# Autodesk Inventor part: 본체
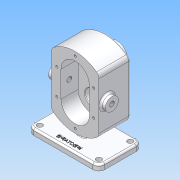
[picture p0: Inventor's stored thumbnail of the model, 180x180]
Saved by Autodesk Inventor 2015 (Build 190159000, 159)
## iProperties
Created: 2019-03
Part Number: 본체
Material: 일반
Document SubType Name: Modeling
Designer: user
Density: 1 g/cm^3
Appearance: 기본값
Mass: 439.69 g
Surface Area: 719.273 cm^2
Volume: 439.69 cm^3
Author: user
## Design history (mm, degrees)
sketch "스케치1"
  geometry: L1 (-60, 36.5)-(60, 36.5); L2 (60, 36.5)-(60, -36.5); L3 (60, -36.5)-(-60, -36.5); L4 (-60, -36.5)-(-60, 36.5); L5 (-60, 36.5)-(60, -36.5); L6 (60, 36.5)-(-60, -36.5); 1 further point
  constraints: 12 end point, 2 midpoint, 2 parallel, 1 horizontal, 1 perpendicular
  dimensions: "d0" = 120 distance of L2.end L3.end; "d1" = 73 distance of L1.end L2.end
extrude "돌출1" new body sketch "스케치1" distance "d2" = 10; taper "d3" = 0 deg
fillet "모깎기1" dims "d4" = 10
hole "구멍1" diameter "d8" = 9; stored, may be unused: countersink angle "d12" = 90 deg, drill point angle "d14" = 0 deg; dims "d6" = 10, "d7" = 10, "d9" = 6, "d10" = 4, "d11" = 2, "d13" = 8
hole "구멍2" diameter "d17" = 9; stored, may be unused: countersink angle "d21" = 90 deg, drill point angle "d23" = 0 deg; dims "d15" = 10, "d16" = 10, "d18" = 6, "d19" = 4, "d20" = 2, "d22" = 8
hole "구멍3" diameter "d26" = 9; stored, may be unused: countersink angle "d30" = 90 deg, drill point angle "d32" = 0 deg; dims "d24" = 10, "d25" = 10, "d27" = 6, "d28" = 4, "d29" = 2, "d31" = 8
hole "구멍4" diameter "d35" = 9; stored, may be unused: countersink angle "d39" = 90 deg, drill point angle "d41" = 0 deg; dims "d33" = 10, "d34" = 10, "d36" = 6, "d37" = 4, "d38" = 2, "d40" = 8
sketch "스케치2"
  geometry: L1 (50, 36.5)-(-50, 36.5) reference; L2 (-6, -6.5)-(6, -6.5); L3 (6, -6.5)-(6, 36.5); L4 (6, 36.5)-(-6, 36.5); L5 (-6, 36.5)-(-6, -6.5); 2 further points
  constraints: 8 end point, 2 midpoint, 2 parallel, 1 horizontal, 1 perpendicular, 1 point on line
  dimensions: "d42" = 43 distance of L2.end L3.end; "d43" = 12 distance of L2.start L2.end
extrude "돌출2" join sketch "스케치2" distance "d44" = 30; taper "d45" = 0 deg
fillet "모깎기3" dims "d46" = 3
sketch "스케치3"
  geometry: L1 (0, 0)-(100, 0) reference; L2 (90, -122.721)-(90, -33.279); L3 (10, -122.721)-(10, -33.279); A1 r 60 centre (50, -78) between (10, -122.721) and (90, -122.721); A2 r 60 centre (50, -78) between (90, -33.279) and (10, -33.279); 2 further points
  constraints: 6 point on circle, 4 end point, 2 centre point, 2 horizontal alignment, 2 vertical, 1 coincident, 1 midpoint, 1 point on line, 1 vertical alignment
  dimensions: "d47" = 60 radius of A1; "d48" = 78 distance of point (50, 0) A1.centre; "d49" = 60 radius of A2; "d50" = 80 distance between parallel lines of L3 L2
extrude "돌출3" join sketch "스케치3" distance "d51" = 53; taper "d52" = 0 deg
fillet "모깎기4" dims "d53" = 10
sketch "스케치4"
  geometry: L1 (100, 0)-(0, 0) reference; L2 (26, 56)-(26, 100); L3 (74, 100)-(74, 56); A1 r 60 centre (50, 78) between (14, 30) and (86, 30) reference; A2 r 24 centre (50, 100) between (74, 100) and (26, 100); A3 r 24 centre (50, 56) between (26, 56) and (74, 56); 1 further point
  constraints: 4 end point, 4 point on circle, 4 tangent, 2 centre point, 2 vertical alignment, 1 parallel, 1 vertical
  dimensions: "d58" = 24 radius of A2; "d59" = 44 distance of A3.centre A2.centre; "d60" = 22 distance of A2.centre A1.centre
extrude "돌출4" cut sketch "스케치4" distance "d61" = 29; taper "d62" = 0 deg
sketch "스케치5"
  geometry: C1 r 12.5 at (50, 100); A1 r 24 centre (50, 100) between (74, 100) and (26, 100) reference; 1 further point
  constraints: 1 centre point, 1 coincident
  dimensions: "d63" = 25 diameter of C1
extrude "돌출5" cut sketch "스케치5" distance "d64" = 15; taper "d65" = 0 deg
sketch "스케치6"
  geometry: C1 r 12.5 at (50, 56); A1 r 24 centre (50, 56) between (26, 56) and (74, 56) reference; 1 further point
  constraints: 1 centre point, 1 coincident
  dimensions: "d66" = 25 diameter of C1
extrude "돌출6" cut sketch "스케치6" distance "d67" = 15; taper "d68" = 0 deg
chamfer "모따기1" distance "d69" = 1; stored, may be unused: second distance "d70" = 2, angle "d71" = 45 deg
sketch "스케치7"
  geometry: C1 r 19 at (50, -100); A1 r 60 centre (50, -78) between (14, -126) and (86, -126) reference; 1 further point
  constraints: 1 centre point, 1 vertical alignment
  dimensions: "d72" = 38 diameter of C1; "d73" = 100 distance of point (50, 0) C1.centre
extrude "돌출7" join sketch "스케치7" distance "d74" = 17; taper "d75" = 0 deg
node "작업 평면1"
sketch "스케치8"
  geometry: L1 (53.5, 81)-(53.5, 119) reference; L2 (53.5, 114.404)-(52.8, 114); L3 (52.8, 114)-(52.8, 100); L4 (52.8, 114)-(51.613, 114); L5 (52.8, 100)-(53.5, 100); L6 (53.5, 114.404)-(53.5, 100); 1 further point
  constraints: 10 end point, 2 midpoint, 2 point on line, 1 collinear, 1 horizontal, 1 perpendicular, 1 vertical
  dimensions: "d76" = 30 deg angle of L4 L2; "d78" = 0.7 distance of L3.end L5.end; "d79" = 14 distance of L2.end L3.end
revolve "회전1" sketch "스케치8" stored, may be unused: angle "d80" = 90 deg
sketch "스케치9"
  geometry: L1 (52.8, 114)-(52.8, 86) reference; L2 (52.8, 114)-(46.2, 114); L3 (46.2, 114)-(46.2, 100); L4 (46.2, 100)-(52.8, 100); 2 further points
  constraints: 6 end point, 2 midpoint, 2 perpendicular, 1 horizontal, 1 point on line
  dimensions: "d81" = 6.6 distance of L3.end L4.end; "d82" = 14 distance of L2.end L3.end (derived)
revolve "회전2" sketch "스케치9" stored, may be unused: angle "d83" = 90 deg
fillet "모깎기5" dims "d84" = 0.5
hole "구멍5" diameter "d87" = 17; stored, may be unused: countersink angle "d91" = 90 deg, drill point angle "d93" = 0 deg; dims "d85" = 10, "d86" = 10, "d88" = 6, "d89" = 4, "d90" = 2, "d92" = 8
sketch "스케치10"
  geometry: L1 (80, -53)-(0, -53) reference; L2 (118, -10)-(118, -63) reference; C1 r 11 at (40, -39); 1 further point
  constraints: 1 centre point
  dimensions: "d94" = 22 diameter of C1; "d95" = 14 distance from line of C1.centre L1; "d96" = 78 distance from line of L2 C1.centre
extrude "돌출8" join sketch "스케치10" distance "d97" = 8; taper "d98" = 0 deg
fillet "모깎기6" dims "d99" = 3
hole "구멍6" diameter "d102" = 8.376; stored, may be unused: countersink angle "d106" = 90 deg, drill point angle "d108" = 0 deg; dims "d103" = 30, "d104" = 4, "d105" = 2, "d107" = 37.3, "d111" = 10, "d112" = 10
fillet "모깎기7" dims "d109" = 3
fillet "모깎기8" dims "d110" = 3
sketch "스케치11"
  geometry: L1 (19, 100)-(19, 56); L2 (81, 56)-(81, 100); A1 r 24 centre (50, 56) between (26, 56) and (74, 56) reference; A2 r 24 centre (50, 100) between (74, 100) and (26, 100) reference; A3 r 31 centre (50, 100) between (81, 100) and (19, 100); A4 r 31 centre (50, 56) between (19, 56) and (81, 56); 7 further points
  constraints: 6 coincident, 6 point on circle, 4 end point, 2 centre point, 2 tangent, 1 parallel, 1 vertical
  dimensions: "d113" = 31 radius of A3; "d114" = 31 radius of A4
hole "구멍7" sketch "스케치11" at (50, 131), (19, 100), (81, 100), (81, 56), (19, 56), (50, 25) diameter "d116" = 4.134; stored, may be unused: countersink angle "d120" = 90 deg, drill point angle "d122" = 118 deg; dims "d117" = 10, "d118" = 4, "d119" = 2, "d121" = 12
node "작업 평면2"
sketch "스케치12"
  geometry: L1 (-60, 26.5)-(-60, -26.5) reference; L2 (-50, -36.5)-(50, -36.5) reference; 2 further points
  constraints: 1 other
  dimensions: "d124" = 60 distance from line of L1 point (0, -26.5); "d125" = 10 distance from line of point (0, -26.5) L2
feature "엠보싱1" sketch "스케치12" dims "d126" = 0.5, "d127" = 0
node "솔리드1"
mirror "대칭1"
mirror "대칭2"
other parameters: "d123" = 11.5
